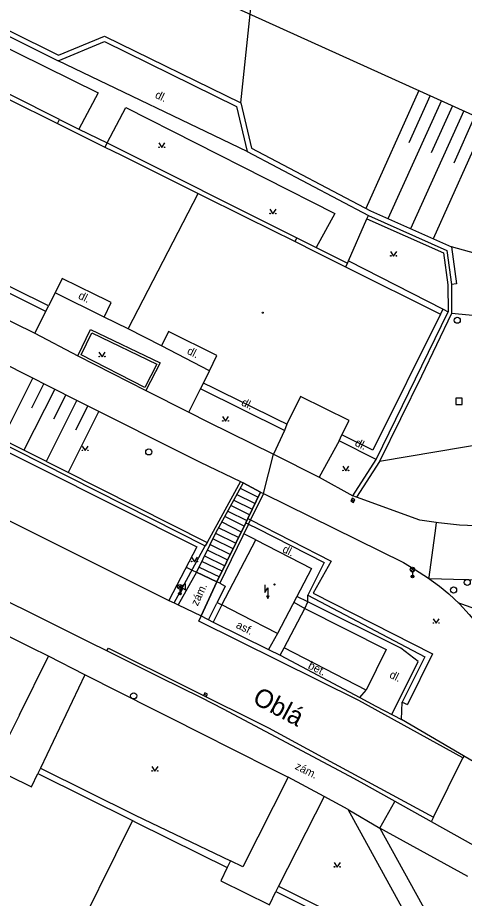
# Model space of a CAD drawing. Extents: x -602419 to -601554, y -1162937 to -1162362.
# Drawn here: x -602069.2 to -602032.9, y -1162500.8 to -1162429.2 of the extents above; entities that cross this region are included whole.
import ezdxf

# ---------------------------------------------------------------- set-up
doc = ezdxf.new("R2010")
doc.units = 0
doc.layers.add('Podklad', color=7, linetype='Continuous')

msp = doc.modelspace()

# ---------------------------------------------------------------- linework, layer by layer
at = {"layer": 'Podklad'}
for p, q in [((-602042.0495, -1162468.3896), (-602041.8305, -1162468.5104)), ((-602037.2225, -1162474.2), (-602036.9575, -1162473.935)), ((-602037.2225, -1162473.935), (-602036.9575, -1162474.2)), ((-602037.09, -1162474.255), (-602037.09, -1162474.63)), ((-602056.1325, -1162475.6), (-602055.8675, -1162475.335)), ((-602056.1325, -1162475.335), (-602055.8675, -1162475.6)), ((-602055.7455, -1162475.5892), (-602056, -1162476.03)), ((-602056, -1162475.655), (-602056, -1162476.03)), ((-602056.1083, -1162475.9675), (-602055.8917, -1162476.0925)), ((-602054.0213, -1162484.1833), (-602053.7985, -1162484.2967))]:
    msp.add_line(p, q, dxfattribs=at)
for points in [[(-602107.1599, -1162403.26), (-602014, -1162445.37)], [(-602110.59, -1162410.03), (-602105.99, -1162412.28), (-602092.51, -1162419.02), (-602085.79, -1162422.38), (-602065.86, -1162432.31), (-602062.11, -1162430.76), (-602051.04, -1162436.18), (-602050.17, -1162439.85), (-602040.49, -1162444.95), (-602033.93, -1162447.87), (-602033.51, -1162450.86), (-602033.9099, -1162450.92)], [(-602110.75, -1162410.35), (-602085.9699, -1162422.74), (-602065.88, -1162432.75)], [(-602051.04, -1162436.18), (-602050.2751, -1162428.9729), (-602049.7199, -1162423.74)], [(-602081.53, -1162429.62), (-602080.07, -1162426.74), (-602062.63, -1162435.36), (-602064.21, -1162438.3)], [(-602065.79, -1162437.52), (-602081.53, -1162429.62)], [(-602065.88, -1162432.75), (-602062.12, -1162431.2), (-602051.39, -1162436.46), (-602050.52, -1162440.12)], [(-602050.52, -1162440.12), (-602065.88, -1162432.75)], [(-602074.05, -1162433.83), (-602065.95, -1162437.85)], [(-602036.57, -1162435.17), (-602040.89, -1162444.74)], [(-602035.6599, -1162435.58), (-602037.39, -1162439.42)], [(-602034.74, -1162435.99), (-602039.08, -1162445.58)], [(-602033.83, -1162436.4099), (-602035.56, -1162440.24)], [(-602061.9099, -1162439.42), (-602060.38, -1162436.55), (-602043.39, -1162445.15), (-602044.9099, -1162447.92)], [(-602032.92, -1162436.82), (-602037.25, -1162446.39)], [(-602032.01, -1162437.23), (-602033.74, -1162441.06)], [(-602065.95, -1162437.85), (-602065.79, -1162437.52)], [(-602065.95, -1162437.85), (-602064.31, -1162438.67)], [(-602065.79, -1162437.52), (-602064.21, -1162438.3)], [(-602031.1, -1162437.64), (-602035.42, -1162447.21)], [(-602064.31, -1162438.67), (-602062.09, -1162439.76)], [(-602064.21, -1162438.3), (-602061.9099, -1162439.42)], [(-602061.9099, -1162439.42), (-602062.09, -1162439.76)], [(-602062.09, -1162439.76), (-602060.8, -1162440.4)], [(-602061.9099, -1162439.42), (-602046.48, -1162447.14)], [(-602057.71, -1162439.425), (-602057.46, -1162439.8), (-602057.21, -1162439.425)], [(-602060.8, -1162440.4), (-602054.52, -1162443.52)], [(-602050.52, -1162440.12), (-602040.67, -1162445.31)], [(-602060.2, -1162454.53), (-602054.52, -1162443.52)], [(-602054.52, -1162443.52), (-602050.58, -1162445.48)], [(-602048.68, -1162444.815), (-602048.43, -1162445.19), (-602048.18, -1162444.815)], [(-602119.69, -1162445.21), (-602056.89, -1162476.59)], [(-602050.58, -1162445.48), (-602046.63, -1162447.44)], [(-602042.3, -1162449), (-602040.79, -1162445.58)], [(-602040.79, -1162445.58), (-602040.67, -1162445.31)], [(-602040.79, -1162445.58), (-602034.57, -1162448.35), (-602034.21, -1162450.94), (-602034.19, -1162453.14)], [(-602040.67, -1162445.31), (-602034.3, -1162448.15), (-602033.9099, -1162450.92)], [(-602046.63, -1162447.44), (-602046.48, -1162447.14)], [(-602046.48, -1162447.14), (-602044.9099, -1162447.92)], [(-602046.63, -1162447.44), (-602044.9699, -1162448.27)], [(-602044.9099, -1162447.92), (-602042.38, -1162449.18)], [(-602009.8073, -1162454.5516), (-602033.93, -1162447.87)], [(-602044.9699, -1162448.27), (-602042.52, -1162449.49)], [(-602038.87, -1162448.245), (-602038.62, -1162448.62), (-602038.37, -1162448.245)], [(-602067.01, -1162452.49), (-602073.46, -1162449.31)], [(-602042.38, -1162449.18), (-602042.52, -1162449.49)], [(-602042.38, -1162449.18), (-602042.3, -1162449)], [(-602042.3, -1162449), (-602034.6, -1162452.93)], [(-602066.89, -1162453.11), (-602073.67, -1162449.76)], [(-602042.52, -1162449.49), (-602034.8, -1162453.32)], [(-602065.57, -1162450.44), (-602066.13, -1162451.59)], [(-602062.9, -1162451.74), (-602065.57, -1162450.44)], [(-602067.6599, -1162477.83), (-602078.96, -1162472.25), (-602083.03, -1162470.23), (-602092.86, -1162465.34), (-602100.43, -1162461.58), (-602105.24, -1162459.2), (-602114.08, -1162454.79), (-602118.63, -1162452.48), (-602121.19, -1162451.25)], [(-602033.9099, -1162450.92), (-602033.92, -1162453.27)], [(-602074.54, -1162451.58), (-602067.79, -1162454.88)], [(-602066.13, -1162451.59), (-602066.6599, -1162452.6599)], [(-602062.15, -1162453.56), (-602066.13, -1162451.59)], [(-602061.96, -1162452.2), (-602062.9, -1162451.74)], [(-602061.57, -1162452.39), (-602061.96, -1162452.2)], [(-602066.6599, -1162452.6599), (-602067.01, -1162452.49)], [(-602066.89, -1162453.11), (-602066.6599, -1162452.6599)], [(-602062.15, -1162453.56), (-602061.57, -1162452.39)], [(-602034.8, -1162453.32), (-602034.6, -1162452.93)], [(-602034.6, -1162452.93), (-602034.19, -1162453.14)], [(-602067.79, -1162454.88), (-602066.89, -1162453.11)], [(-602060.2, -1162454.53), (-602062.15, -1162453.56)], [(-602034.8, -1162453.32), (-602040.31, -1162464.37)], [(-602040.04, -1162465.13), (-602034.19, -1162453.14)], [(-602033.92, -1162453.27), (-602036.36, -1162458.37), (-602039.78, -1162465.28)], [(-602010.43, -1162455.5), (-602033.92, -1162453.27)], [(-602076.24, -1162454.32), (-602064.46, -1162460.28), (-602054.34, -1162465.34), (-602051.08, -1162466.92)], [(-602089.04, -1162454.93), (-602080.77, -1162459.12), (-602054.62, -1162472.2199), (-602056.89, -1162476.59), (-602056.46, -1162476.78)], [(-602067.79, -1162454.88), (-602064.29, -1162456.7199)], [(-602064.29, -1162456.7199), (-602063.26, -1162454.57), (-602057.59, -1162457.29), (-602058.77, -1162459.54)], [(-602058.85, -1162459.27), (-602064.03, -1162456.63), (-602063.1599, -1162454.84), (-602057.86, -1162457.38), (-602058.85, -1162459.27)], [(-602057.5, -1162455.9), (-602060.2, -1162454.53)], [(-602056.93, -1162454.74), (-602057.5, -1162455.9)], [(-602052.98, -1162456.68), (-602056.93, -1162454.74)], [(-602010.43, -1162455.5), (-602028.35, -1162463.37), (-602039.78, -1162465.28)], [(-602062.57, -1162456.425), (-602062.32, -1162456.8), (-602062.07, -1162456.425)], [(-602053.6, -1162457.94), (-602057.5, -1162455.9)], [(-602064.29, -1162456.7199), (-602058.77, -1162459.54)], [(-602053.6, -1162457.94), (-602052.98, -1162456.68)], [(-602079.76, -1162457.5), (-602080.4099, -1162458.78), (-602053.93, -1162472.14)], [(-602079.34, -1162457.34), (-602080, -1162458.65), (-602053.79, -1162471.88)], [(-602054.08, -1162458.92), (-602053.6, -1162457.94)], [(-602067.95, -1162458.51), (-602070.45, -1162463.4699)], [(-602066.1599, -1162459.42), (-602068.67, -1162464.37)], [(-602067.06, -1162458.9699), (-602068.06, -1162460.95)], [(-602055.26, -1162461.28), (-602054.31, -1162459.38)], [(-602054.31, -1162459.38), (-602054.08, -1162458.92)], [(-602047.5, -1162462.78), (-602054.31, -1162459.38)], [(-602053.23, -1162459.34), (-602054.08, -1162458.92)], [(-602048.02, -1162461.9), (-602053.23, -1162459.34)], [(-602065.27, -1162459.87), (-602066.27, -1162461.85)], [(-602058.77, -1162459.54), (-602055.26, -1162461.28)], [(-602046.19, -1162460.01), (-602047.3, -1162462.25)], [(-602042.24, -1162461.96), (-602046.19, -1162460.01)], [(-602064.38, -1162460.32), (-602066.86, -1162465.28)], [(-602063.48, -1162460.77), (-602064.48, -1162462.75)], [(-602062.59, -1162461.21), (-602065.07, -1162466.18)], [(-602055.26, -1162461.28), (-602053.73, -1162462.06)], [(-602053.73, -1162462.06), (-602048.38, -1162464.69)], [(-602052.53, -1162461.645), (-602052.28, -1162462.02), (-602052.03, -1162461.645)], [(-602047.3, -1162462.25), (-602048.02, -1162461.9)], [(-602047.3, -1162462.25), (-602047.5, -1162462.78)], [(-602042.82, -1162463.13), (-602042.24, -1162461.96)], [(-602047.5, -1162462.78), (-602048.38, -1162464.69)], [(-602013.84, -1162462.78), (-602014.46, -1162463.8), (-602015.34, -1162464.92), (-602016.43, -1162466.08), (-602017.87, -1162467.23), (-602018.85, -1162467.87), (-602020.28, -1162468.58), (-602021.27, -1162468.9699), (-602022.42, -1162469.31), (-602023.42, -1162469.5), (-602025.4, -1162469.9699), (-602027.4099, -1162470.28), (-602029.93, -1162470.5), (-602031.35, -1162470.53), (-602033.26, -1162470.45), (-602034.98, -1162470.28), (-602036.5, -1162470.05)], [(-602043.06, -1162463.61), (-602044.67, -1162466.56)], [(-602043.06, -1162463.61), (-602042.82, -1162463.13)], [(-602040.04, -1162465.13), (-602043.06, -1162463.61)], [(-602040.31, -1162464.37), (-602042.82, -1162463.13)], [(-602063.94, -1162464.0349), (-602063.69, -1162464.4099), (-602063.44, -1162464.0349)], [(-602049.21, -1162467.88), (-602048.38, -1162464.69), (-602044.67, -1162466.56)], [(-602041.93, -1162468.08), (-602040.04, -1162465.13)], [(-602042.76, -1162465.665), (-602042.51, -1162466.04), (-602042.26, -1162465.665)], [(-602039.78, -1162465.28), (-602041.64, -1162468.19)], [(-602044.67, -1162466.56), (-602041.93, -1162468.08)], [(-602050.86, -1162467.03), (-602052.68, -1162470.38), (-602053.06, -1162471.06), (-602054.65, -1162474.28)], [(-602051.08, -1162466.92), (-602053.79, -1162471.88)], [(-602050.86, -1162467.03), (-602052.68, -1162470.38), (-602053.06, -1162471.06)], [(-602051.08, -1162466.92), (-602050.86, -1162467.03)], [(-602049.44, -1162467.77), (-602050.86, -1162467.03)], [(-602050.86, -1162467.03), (-602049.44, -1162467.77)], [(-602049.89, -1162468.7), (-602051.38, -1162467.98)], [(-602051.09, -1162467.45), (-602049.64, -1162468.19)], [(-602049.44, -1162467.77), (-602050.4699, -1162469.9099)], [(-602050.4699, -1162469.9099), (-602049.44, -1162467.77)], [(-602049.21, -1162467.88), (-602050.25, -1162470.02)], [(-602049.44, -1162467.77), (-602049.21, -1162467.88)], [(-602049.21, -1162467.88), (-602037.82, -1162473.49), (-602036.85, -1162474.09)], [(-602051.62, -1162468.42), (-602050.11, -1162469.1599)], [(-602041.64, -1162468.19), (-602041.93, -1162468.08)], [(-602036.5, -1162470.05), (-602041.64, -1162468.19)], [(-602052.1, -1162469.32), (-602050.56, -1162470.09)], [(-602050.33, -1162469.63), (-602051.86, -1162468.87)], [(-602050.78, -1162470.55), (-602052.35, -1162469.77)], [(-602050.4699, -1162469.9099), (-602050.64, -1162470.26)], [(-602050.64, -1162470.26), (-602050.4699, -1162469.9099)], [(-602050.4699, -1162469.9099), (-602050.25, -1162470.02)], [(-602050.4174, -1162470.3714), (-602050.2474, -1162470.0214)], [(-602050.25, -1162470.02), (-602043.69, -1162473.38), (-602045.15, -1162475.98), (-602035.46, -1162480.9), (-602037.5, -1162485.03)], [(-602050.64, -1162470.26), (-602052.98, -1162475.07)], [(-602052.98, -1162475.07), (-602050.64, -1162470.26)], [(-602050.42, -1162470.37), (-602052.75, -1162475.18), (-602052.98, -1162475.07)], [(-602051.2199, -1162471.46), (-602052.85, -1162470.68)], [(-602052.58, -1162470.2), (-602051, -1162471)], [(-602050.64, -1162470.26), (-602050.42, -1162470.37)], [(-602050.42, -1162470.37), (-602049.69, -1162470.74), (-602044.26, -1162473.5), (-602045.59, -1162476.15), (-602036.09, -1162481.14), (-602037.93, -1162484.84)], [(-602035.7356, -1162474.8093), (-602035.72, -1162474.69), (-602035.1971, -1162470.6919), (-602035.1403, -1162470.2557)], [(-602053.06, -1162471.06), (-602054.65, -1162474.28)], [(-602051.67, -1162472.37), (-602053.31, -1162471.57)], [(-602053.09, -1162471.12), (-602051.45, -1162471.92)], [(-602049.82, -1162471.64), (-602050.8082, -1162471.1713)], [(-602056.46, -1162476.78), (-602053.93, -1162472.14)], [(-602053.78, -1162471.88), (-602053.93, -1162472.14)], [(-602053.79, -1162471.88), (-602053.78, -1162471.88)], [(-602053.54, -1162472.03), (-602051.89, -1162472.83)], [(-602052.59, -1162476.92), (-602049.82, -1162471.64)], [(-602049.82, -1162471.64), (-602045.29, -1162473.98)], [(-602068.1, -1162480.4), (-602083.08, -1162472.9099), (-602087.02, -1162480.43)], [(-602053.99, -1162472.95), (-602052.34, -1162473.75)], [(-602052.11, -1162473.29), (-602053.76, -1162472.49)], [(-602055.06, -1162473.065), (-602054.81, -1162473.44), (-602054.56, -1162473.065)], [(-602052.56, -1162474.21), (-602054.2199, -1162473.4099)], [(-602054.65, -1162474.28), (-602056.13, -1162476.92)], [(-602055.476, -1162473.8679), (-602055.0008, -1162474.1039), (-602054.65, -1162474.28), (-602052.98, -1162475.07)], [(-602052.98, -1162475.07), (-602054.65, -1162474.28)], [(-602054.44, -1162473.86), (-602052.78, -1162474.6599)], [(-602045.29, -1162473.98), (-602048.07, -1162479.27)], [(-602036.85, -1162474.09), (-602035.86, -1162474.7199), (-602034.9, -1162475.4099), (-602034.14, -1162476.05), (-602033.28, -1162476.86), (-602032.4699, -1162477.7199), (-602031.84, -1162478.48)], [(-602052.98, -1162475.07), (-602054.26, -1162477.83)], [(-602054.26, -1162477.83), (-602052.98, -1162475.07)], [(-602025.79, -1162475.08), (-602035.7356, -1162474.8093)], [(-602052.75, -1162475.18), (-602052.317, -1162475.4099), (-602052.9745, -1162476.745), (-602053.0008, -1162476.7985)], [(-602049.1, -1162475.3), (-602049.1, -1162475.925), (-602048.85, -1162475.55), (-602048.85, -1162476.425)], [(-602048.9595, -1162476.1805), (-602048.85, -1162476.425), (-602048.7405, -1162476.1805)], [(-602038.78, -1162485.83), (-602036.63, -1162481.53), (-602038.04, -1162480.45), (-602045.6, -1162476.68), (-602046.48, -1162476.25)], [(-602045.85, -1162477.23), (-602045.6, -1162476.68), (-602045.59, -1162476.15)], [(-602056.46, -1162476.78), (-602056.13, -1162476.92)], [(-602056.13, -1162476.92), (-602054.26, -1162477.83)], [(-602053.6705, -1162478.137), (-602053.0008, -1162476.7985)], [(-602052.59, -1162476.92), (-602053.3, -1162478.33)], [(-602052.9745, -1162476.745), (-602052.59, -1162476.92)], [(-602051.01, -1162477.74), (-602052.59, -1162476.92)], [(-602047.52, -1162480.42), (-602045.85, -1162477.23)], [(-602046.7257, -1162476.7119), (-602045.85, -1162477.23)], [(-602045.85, -1162477.23), (-602039.24, -1162480.57)], [(-602027.24, -1162478.9699), (-602033.08, -1162476.8699), (-602033.3865, -1162476.7597)], [(-602057.59, -1162482.82), (-602067.6599, -1162477.83)], [(-602032.99, -1162489.3599), (-602041.45, -1162484.6899), (-602054.45, -1162478.2499), (-602054.29, -1162477.8999), (-602054.26, -1162477.83)], [(-602054.26, -1162477.83), (-602053.3, -1162478.33)], [(-602048.07, -1162479.27), (-602051.01, -1162477.74)], [(-602053.3, -1162478.33), (-602048.78, -1162480.57)], [(-602035.4099, -1162478.055), (-602035.1599, -1162478.43), (-602034.9099, -1162478.055)], [(-602048.07, -1162479.27), (-602048.78, -1162480.57)], [(-602066.68, -1162481.11), (-602068.1, -1162480.4)], [(-602061.9298, -1162480.6695), (-602061.79, -1162480.4399), (-602048.78, -1162486.9299), (-602043.46, -1162489.8101), (-602035.39, -1162494.1799)], [(-602048.78, -1162480.57), (-602047.84, -1162481.03)], [(-602047.84, -1162481.03), (-602047.52, -1162480.42)], [(-602040.86, -1162483.85), (-602047.52, -1162480.42)], [(-602039.24, -1162480.57), (-602040.86, -1162483.85)], [(-602069.04, -1162485.87), (-602066.68, -1162481.11)], [(-602063.73, -1162482.61), (-602066.68, -1162481.11)], [(-602047.84, -1162481.03), (-602041.36, -1162484.46)], [(-602058.04, -1162485.4699), (-602063.73, -1162482.61), (-602067.33, -1162490.2)], [(-602052.46, -1162485.4099), (-602054.24, -1162484.4699), (-602057.59, -1162482.82)], [(-602041.36, -1162484.46), (-602040.86, -1162483.85)], [(-602041.36, -1162484.46), (-602040.08, -1162485.17), (-602037.98, -1162486.24)], [(-602037.98, -1162486.24), (-602037.93, -1162484.84)], [(-602037.93, -1162484.84), (-602037.5, -1162485.03)], [(-602069.04, -1162485.87), (-602070.38, -1162488.58)], [(-602052.9, -1162488.05), (-602058.04, -1162485.4699)], [(-602042.2, -1162490.85), (-602052.46, -1162485.4099)], [(-602030.92, -1162490.38), (-602037.98, -1162486.24)], [(-602052.9, -1162488.05), (-602047.18, -1162490.92)], [(-602035.39, -1162494.1799), (-602032.99, -1162489.3599)], [(-602032.9173, -1162489.2088), (-602032.99, -1162489.3599)], [(-602058.27, -1162490.065), (-602058.02, -1162490.44), (-602057.77, -1162490.065)], [(-602069.88, -1162490.81), (-602068.06, -1162491.71)], [(-602068.06, -1162491.71), (-602067.53, -1162490.63)], [(-602067.33, -1162490.2), (-602067.53, -1162490.63)], [(-602067.53, -1162490.63), (-602059.84, -1162494.45)], [(-602067.33, -1162490.2), (-602059.62, -1162494), (-602051.88, -1162497.7199)], [(-602041.27, -1162491.36), (-602042.2, -1162490.85)], [(-602047.18, -1162490.92), (-602050.89, -1162498.21)], [(-602044.28, -1162492.48), (-602047.1814, -1162490.9226)], [(-602032.09, -1162496.4699), (-602041.27, -1162491.36)], [(-602044.28, -1162492.48), (-602047.9699, -1162499.78)], [(-602042.32, -1162493.55), (-602044.28, -1162492.48)], [(-602042.32, -1162493.55), (-602039.73, -1162495.07), (-602038.5267, -1162492.887)], [(-602041.85, -1162494.4), (-602042.32, -1162493.55)], [(-602059.84, -1162494.45), (-602065.34, -1162505.53)], [(-602059.84, -1162494.45), (-602059.59, -1162494.58)], [(-602034.33, -1162508.09), (-602041.85, -1162494.4)], [(-602035.39, -1162494.1799), (-602035.5391, -1162494.4842), (-602035.5644, -1162494.5359)], [(-602059.59, -1162494.58), (-602054.4099, -1162497.14)], [(-602032.58, -1162499), (-602039.73, -1162495.07), (-602033.87, -1162505.71)], [(-602054.4099, -1162497.14), (-602052.14, -1162498.26)], [(-602051.88, -1162497.7199), (-602052.14, -1162498.26)], [(-602050.89, -1162498.21), (-602051.88, -1162497.7199)], [(-602043.45, -1162497.855), (-602043.2, -1162498.23), (-602042.95, -1162497.855)], [(-602052.14, -1162498.26), (-602052.67, -1162499.34)], [(-602052.67, -1162499.34), (-602048.71, -1162501.29)], [(-602047.9699, -1162499.78), (-602048.19, -1162500.2199)], [(-602047.9699, -1162499.78), (-602040.1, -1162503.69)], [(-602048.71, -1162501.29), (-602048.19, -1162500.2199)], [(-602048.19, -1162500.2199), (-602043.4099, -1162502.59)]]:
    msp.add_lwpolyline(points, dxfattribs=at)
for points in [[(-602033.56, -1162460.6599), (-602033.06, -1162460.6599), (-602033.06, -1162460.1599), (-602033.56, -1162460.1599)], [(-602042.1098, -1162468.4991), (-602041.8909, -1162468.6198), (-602041.7702, -1162468.4009), (-602041.9891, -1162468.2802)], [(-602055.962, -1162475.4642), (-602055.529, -1162475.7142), (-602055.529, -1162475.2142)], [(-602054.078, -1162484.2946), (-602053.8553, -1162484.4081), (-602053.7418, -1162484.1854), (-602053.9645, -1162484.0719)]]:
    msp.add_lwpolyline(points, close=True, dxfattribs=at)
for centre, radius in [((-602057.6851, -1162439.7749), 0.025), ((-602057.2354, -1162439.7749), 0.025), ((-602048.6551, -1162445.1649), 0.025), ((-602048.2054, -1162445.1649), 0.025), ((-602038.8451, -1162448.5949), 0.025), ((-602038.3954, -1162448.5949), 0.025), ((-602049.26, -1162453.21), 0.045), ((-602049.26, -1162453.21), 0.0199), ((-602033.45, -1162453.82), 0.25), ((-602062.5451, -1162456.7749), 0.025), ((-602062.0954, -1162456.7749), 0.025), ((-602052.5051, -1162461.9949), 0.025), ((-602052.0554, -1162461.9949), 0.025), ((-602063.9151, -1162464.3848), 0.025), ((-602063.4654, -1162464.3848), 0.025), ((-602058.52, -1162464.51), 0.25), ((-602042.7351, -1162466.0149), 0.025), ((-602042.2854, -1162466.0149), 0.025), ((-602055.0351, -1162473.4149), 0.025), ((-602054.5854, -1162473.4149), 0.025), ((-602037.09, -1162474.0675), 0.1875), ((-602037.09, -1162474.63), 0.1), ((-602037.09, -1162474.63), 0.0723), ((-602037.09, -1162474.63), 0.0438), ((-602032.64, -1162475.11), 0.25), ((-602056, -1162475.4675), 0.1875), ((-602048.31, -1162475.28), 0.045), ((-602048.31, -1162475.28), 0.0199), ((-602033.75, -1162475.7199), 0.25), ((-602056, -1162476.03), 0.1), ((-602056, -1162476.03), 0.0723), ((-602056, -1162476.03), 0.0438), ((-602035.385, -1162478.4049), 0.025), ((-602034.9353, -1162478.4049), 0.025), ((-602059.75, -1162484.32), 0.25), ((-602058.2451, -1162490.4149), 0.025), ((-602057.7954, -1162490.4149), 0.025), ((-602043.4251, -1162498.2049), 0.025), ((-602042.9754, -1162498.2049), 0.025)]:
    msp.add_circle(centre, radius, dxfattribs=at)

# ---------------------------------------------------------------- texts
for s, height, rotation, p in [('dl.', 0.65, 334.37, (-602058.07, -1162435.73)), ('dl.', 0.65, 333.49, (-602064.31, -1162452.03)), ('dl.', 0.65, 333.49, (-602055.4699, -1162456.52)), ('dl.', 0.65, 333.49, (-602051.06, -1162460.7)), ('dl.', 0.65, 333.49, (-602041.83, -1162463.9699)), ('dl.', 0.65, 333.49, (-602047.7199, -1162472.62)), (' zám.', 0.65, 65.12, (-602054.65, -1162477.29)), ('asf.', 0.65, 333.49, (-602051.49, -1162478.77)), ('bet.', 0.65, 333.49, (-602045.63, -1162482.06)), ('dl.', 0.65, 333.49, (-602039.02, -1162482.81)), ('Oblá', 1.5, 332.07, (-602050.18, -1162484.86)), (' zám.', 0.65, 333.64, (-602046.9099, -1162490.13))]:
    msp.add_text(s, height=height, rotation=rotation, dxfattribs=at).set_placement(p)

doc.saveas('drawing.dxf')
